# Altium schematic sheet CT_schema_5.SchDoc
size 373 x 245 mm
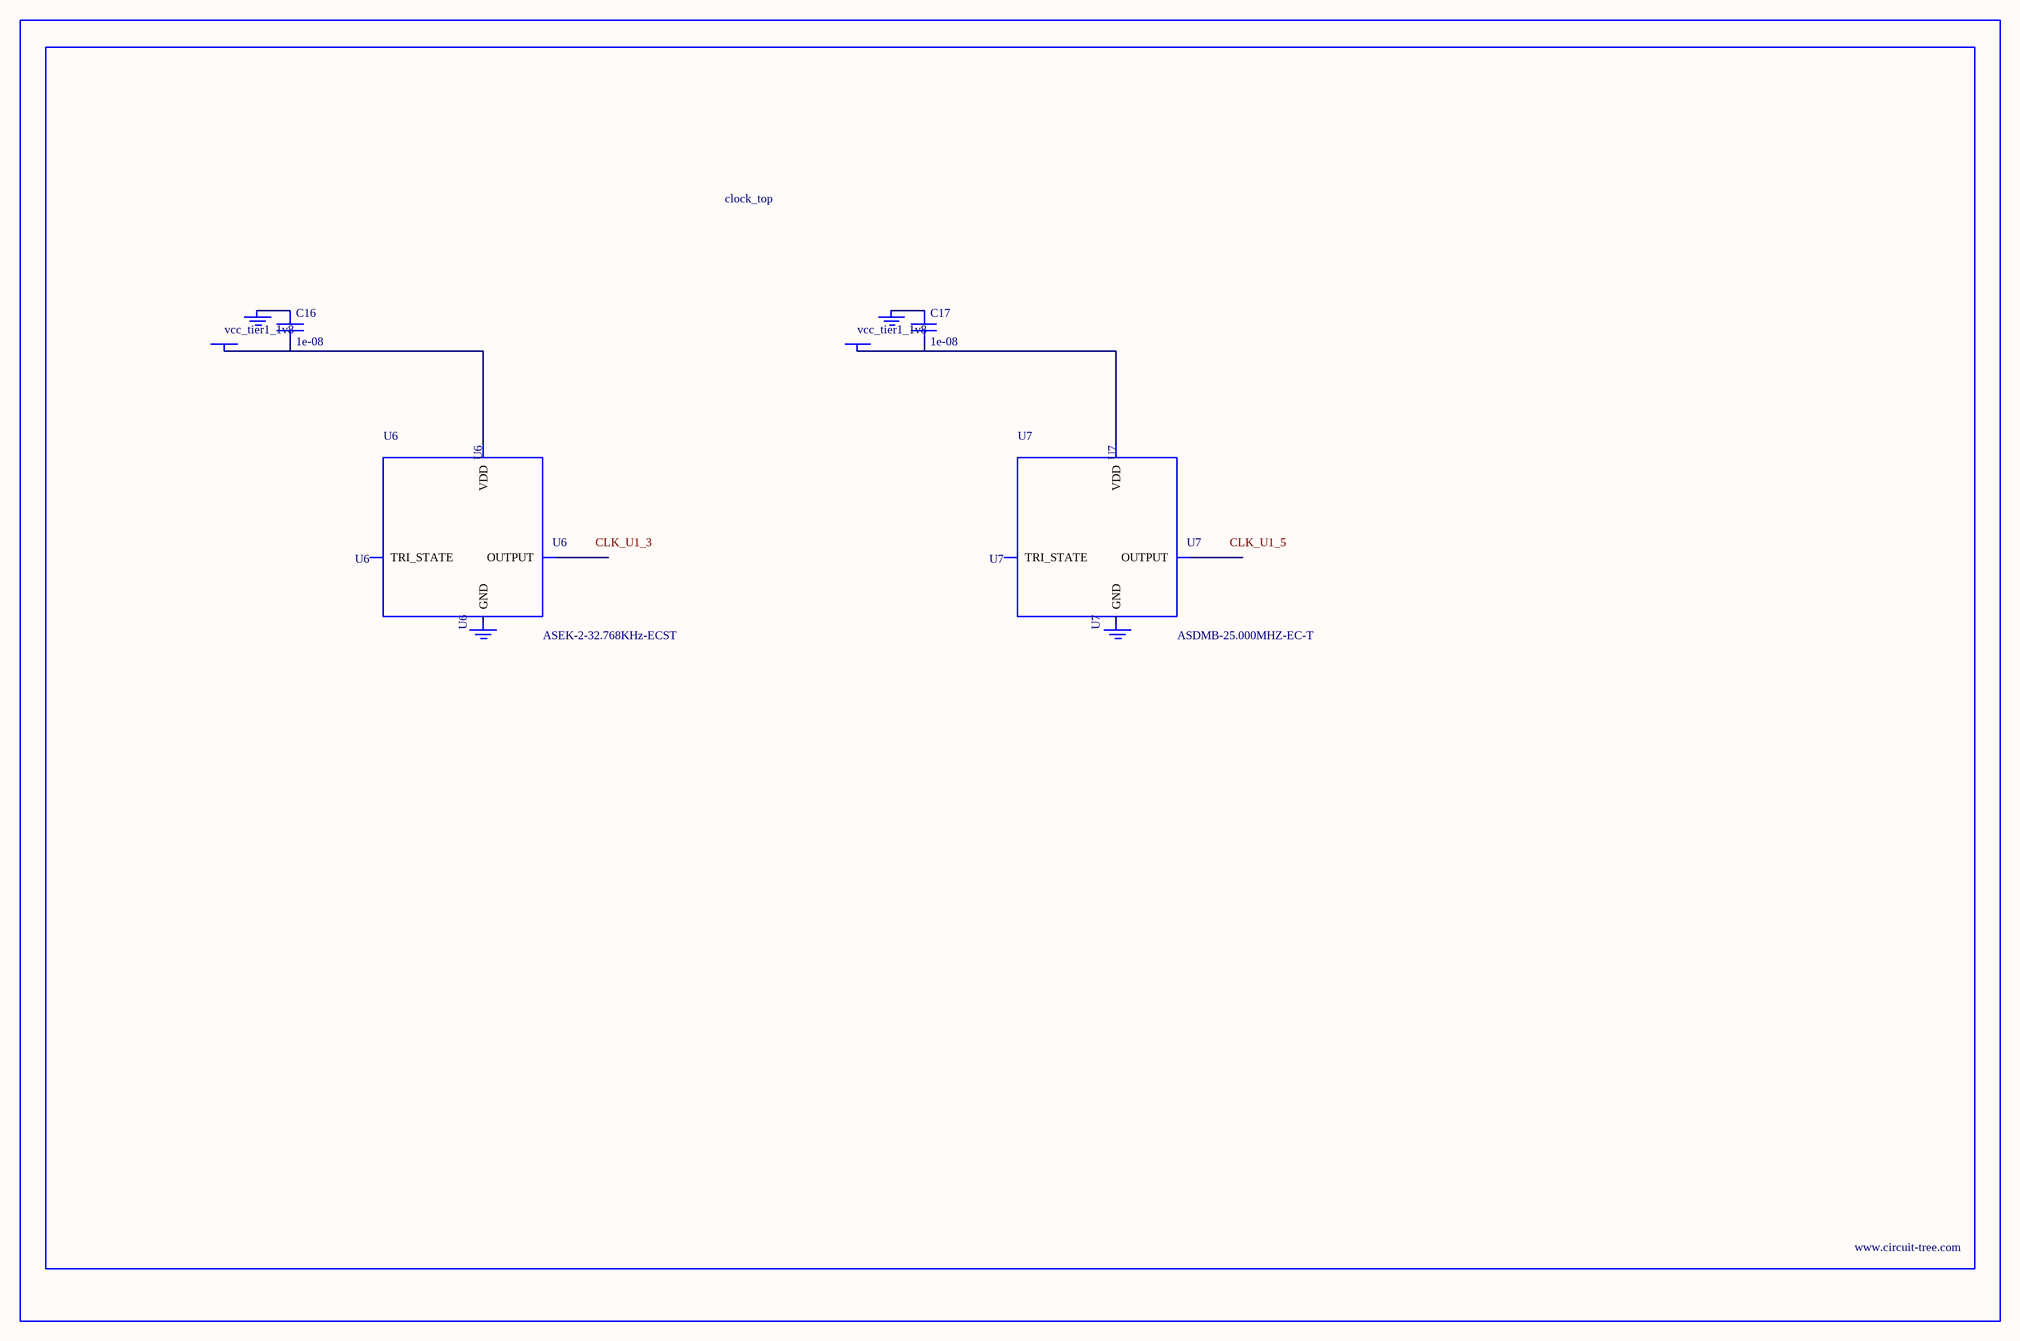
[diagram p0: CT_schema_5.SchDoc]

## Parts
BORDER4  (no value)
C16  1e-08  [C0402]
C17  1e-08  [C0402]
GND_INSTANCE_4_0  (no value)
GND_INSTANCE_4_1  (no value)
GND_INSTANCE_4_2  (no value)
GND_INSTANCE_4_3  (no value)
POWER_INSTANCE_4_0  vcc_tier1_1v8
POWER_INSTANCE_4_1  vcc_tier1_1v8
U6  ASEK-2-32.768KHz-ECST  [ASEK]
U7  ASDMB-25.000MHZ-EC-T  [ASDMB-XX.XXXXMHZ-XX-XX-XXX]

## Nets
NetC16_1: C16.1 GND_INSTANCE_4_0.0(GND)
NetC16_2: C16.2 POWER_INSTANCE_4_0.0(PWR) U6.4(VDD)
NetC17_1: C17.1 GND_INSTANCE_4_2.0(GND)
NetC17_2: C17.2 POWER_INSTANCE_4_1.0(PWR) U7.4(VDD)

Not connected (* = marked no-connect by the designer): GND_INSTANCE_4_1 0(GND); GND_INSTANCE_4_3 0(GND); U6 1(TRI_STATE) 2(GND) 3(OUTPUT); U7 1(TRI_STATE) 2(GND) 3(OUTPUT)

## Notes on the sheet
- Labels drawn without touching a wire or pin: CLK_U1_3, CLK_U1_5

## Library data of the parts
BORDER4 = BORDER_PAGE4
C16 C17 = C0402C103K3RAC
GND_INSTANCE_4_0-GND_INSTANCE_4_3 = GND
POWER_INSTANCE_4_0 POWER_INSTANCE_4_1 = PWR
